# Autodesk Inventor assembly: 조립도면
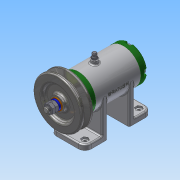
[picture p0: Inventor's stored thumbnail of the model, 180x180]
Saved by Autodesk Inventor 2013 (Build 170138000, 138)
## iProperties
Created: 2017-02
Part Number: 조립도면
Document SubType Name: Assembly
Designer: Administrator
Author: Administrator
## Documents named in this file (16)
- C:\Users\Administrator\Desktop\470207V1023\조립도면.iam
- C:\Users\Administrator\Desktop\470207V1023\1.본체.ipt
- C:\Users\Administrator\Desktop\470207V1023\뒤커버.ipt
- C:\Users\Administrator\Desktop\470207V1023\앞커버.ipt
- C:\Users\Administrator\Desktop\470207V1023\베어링 15 x 32 x 9.ipt
- C:\Users\Administrator\Desktop\470207V1023\축.ipt
- C:\Users\Administrator\Desktop\470207V1023\오일 실 15 25 7.ipt
- C:\Users\Administrator\Desktop\470207V1023\키 3 x 3 x 12.ipt
- C:\Users\Administrator\Desktop\470207V1023\V벨트풀리.ipt
- C:\Users\Administrator\Desktop\470207V1023\와셔 8x17.ipt
- C:\Users\Administrator\Desktop\470207V1023\스프링와셔 8.ipt
- C:\Users\Administrator\Desktop\470207V1023\너트 M 8.ipt
- C:\Users\Administrator\Desktop\470207V1023\니플 M 6 x 0.75.ipt
- C:\Users\Administrator\Desktop\470207V1023\볼트 M4 x 12.ipt
- C:\Users\Administrator\Desktop\470207V1023\와셔 6x11.5.ipt
- C:\Users\Administrator\Desktop\470207V1023\볼트 M 6 x 8.ipt
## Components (12 placed, 4 different names)
1. 1.본체:1
2. KS B 2023 6002 - 15 x 32 x 9:1
3. KS B 2023 6002 - 15 x 32 x 9:2
4. V벨트풀리:1 — 각도:2
5. ISO 4762 M4 x 12:1
6. ISO 4762 M4 x 12:3
7. ISO 4762 M4 x 12:4
8. ISO 4762 M4 x 12:5
9. ISO 4762 M4 x 12:2
10. ISO 4762 M4 x 12:6
11. ISO 4762 M4 x 12:7
12. ISO 4762 M4 x 12:8
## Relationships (1: Angle 1)
- 각도:2 [Angle]: V벨트풀리:1
